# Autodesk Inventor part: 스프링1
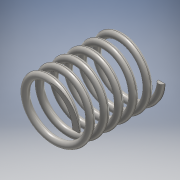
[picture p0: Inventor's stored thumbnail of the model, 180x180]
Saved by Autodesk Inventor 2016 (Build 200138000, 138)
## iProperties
Created: 2019-07
Part Number: 스프링1
Material: 강철, 탄소
Document SubType Name: Modeling
Designer: 602-01
Density: 7.85 g/cm^3
Appearance: 반연마
Mass: 7.77017 g
Surface Area: 20.0872 cm^2
Volume: 0.989831 cm^3
Author: 602-01
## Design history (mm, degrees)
sketch "스케치1"
  geometry: L1 (0, 0)-(8.5, 0); L2 (8.5, 0)-(8.5, 16.67); L3 (8.5, 16.67)-(0, 16.67); L4 (0, 16.67)-(0, 0); C1 r 1 at (8.5, 0)
  constraints: 8 end point, 2 parallel, 1 centre point, 1 coincident, 1 horizontal, 1 perpendicular
  dimensions: "d0" = 17 diameter of L2 L4; "d1" = 16.66987 distance between parallel lines of L1 L3 (derived); "d2" = 2 diameter of C1
feature "코일1" sketch "스케치1" pitch "d3" = 10; turns "d5" = 6; dims "d4" = 16.66987 (= d1), "d6" = 0, angle "d7" = 90 deg, angle "d8" = 90 deg, "d9" = 0, "d10" = 0
sketch "스케치2"
  geometry: L1 (-7.5, 0)-(-9.5, 0) reference; 1 further point
  constraints: 1 horizontal alignment
extrude "돌출1" cut sketch "스케치2" distance "d11" = 10; taper "d12" = 0 deg
node "작업 평면1"
sketch "스케치3"
  geometry: L1 (-1, 0)-(1, 0) reference; 1 further point
  constraints: 1 horizontal alignment
extrude "돌출2" cut sketch "스케치3" distance "d14" = 10; taper "d15" = 0 deg
node "솔리드1"
node "절단 모서리 투영1"
node "절단 모서리 투영2"
other parameters: "d13" = 90 deg
